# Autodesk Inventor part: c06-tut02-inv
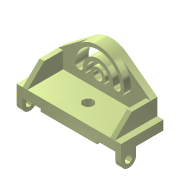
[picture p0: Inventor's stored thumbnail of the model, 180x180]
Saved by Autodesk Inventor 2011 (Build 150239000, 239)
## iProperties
Created: 2010-03
Part Number: c06-tut02-inv
Document SubType Name: Modeling
Designer: CADSoft
Density: 1 g/cm^3
Author: CADSoft
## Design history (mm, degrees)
sketch "Sketch1"
  geometry: 1 further point
sketch "Sketch2"
  geometry: L1 (0, 20)-(-222, 20); L2 (-222, 20)-(-222, 0); L3 (0, 0)-(0, 20); L4 (-171, 0)-(-171, -6); L5 (-171, -6)-(-51, -6); L6 (-51, -6)-(-51, 0); L7 (-222, 0)-(-171, 0); L8 (-51, 0)-(0, 0); 1 further point
  constraints: 16 end point, 4 horizontal, 4 vertical, 2 equal length, 1 coincident
  dimensions: "d0" = 20 distance of L3.start L1.start; "d1" = 26 distance between parallel lines of L5 L1; "d2" = 120 distance of L4.end L5.end; "d3" = 51 distance of L6.end L3.start
extrude "Extrusion1" new body sketch "Sketch2" distance "d4" = 90; taper "d5" = 0 deg
sketch "Sketch3"
  geometry: L1 (209, -20)-(209, -55); L2 (209, -55)-(144.749, -103.524); L3 (77.251, -103.524)-(13, -55); L4 (13, -55)-(13, -20); L5 (13, -20)-(209, -20); L6 (222, -20)-(0, -20) reference; L7 (222, 0)-(222, -20) reference; L8 (0, -20)-(0, 0) reference; A1 r 56 centre (111, -58.836) between (77.251, -103.524) and (144.749, -103.524)
  constraints: 10 end point, 2 equal length, 2 point on circle, 2 tangent, 2 vertical, 1 centre point, 1 horizontal, 1 point on line
  dimensions: "d6" = 35 distance of L1.start L1.end; "d7" = 13 distance between parallel lines of L7 L1; "d8" = 13 distance between parallel lines of L4 L8; "d9" = 56 radius of A1
extrude "Extrusion2" join sketch "Sketch3" distance "d10" = 14; taper "d11" = 0 deg
sketch "Sketch4"
  geometry: C1 r 16 at (111, 58.836); A1 r 56 centre (111, 58.836) between (144.749, 103.524) and (77.251, 103.524) reference; A2 r 24 centre (111, 58.836) between (135, 58.836) and (87, 58.836); A3 r 56 centre (111, 58.836) between (167, 58.836) and (55, 58.836); A4 r 16 centre (71, 58.836) between (55, 58.836) and (87, 58.836); A5 r 16 centre (151, 58.836) between (135, 58.836) and (167, 58.836); 1 further point
  constraints: 8 point on circle, 5 centre point, 4 tangent, 3 coincident, 2 horizontal alignment
  dimensions: "d12" = 56 radius of A3; "d14" = 24 radius of A2; "d15" = 32 diameter of C1
extrude "Extrusion3" join sketch "Sketch4" distance "d16" = 14; taper "d17" = 0 deg
sketch "Sketch5"
  geometry: C1 r 9 at (111, 58.836); A1 r 16 centre (151, 58.836) between (135, 58.836) and (167, 58.836) reference; A2 r 56 centre (111, 58.836) between (167, 58.836) and (55, 58.836) reference; A3 r 16 centre (71, 58.836) between (55, 58.836) and (87, 58.836) reference; A4 r 24 centre (111, 58.836) between (135, 58.836) and (87, 58.836) reference; A5 r 48 centre (111, 58.836) between (159, 58.836) and (63, 58.836); A6 r 8 centre (151, 58.836) between (143, 58.836) and (159, 58.836); A7 r 32 centre (111, 58.836) between (143, 58.836) and (79, 58.836); A8 r 8 centre (71, 58.836) between (63, 58.836) and (79, 58.836); 1 further point
  constraints: 8 point on circle, 5 centre point, 1 coincident, 3 other
  dimensions: "d18" = 8 radius of A8; "d19" = 18 diameter of C1
extrude "Extrusion4" cut sketch "Sketch5" stored distance "d20" = 14; taper "d21" = 0 deg
sketch "Sketch6"
  geometry: L1 (35, -90)-(0, -54); L2 (0, -54)-(0, -14); 2 further points
  constraints: 4 end point, 1 coincident
  dimensions: "d22" = 40 distance of L1.end L2.end
feature "Rib1" sketch "Sketch6" dims "d23" = 1, "d24" = 10, "d25" = 0
sketch "Sketch7"
  geometry: L1 (0, 0)-(0, 90) reference; L2 (0, 0)-(0, 32); L3 (0, 32)-(36, 32); L4 (36, 0)-(0, 0); C1 r 8 at (36, 16); A1 r 16 centre (36, 16) between (36, 0) and (36, 32)
  constraints: 6 end point, 2 centre point, 2 horizontal, 2 point on circle, 2 tangent, 1 coincident, 1 point on line
  dimensions: "d26" = 36 distance of L4.start L1.start; "d27" = 16 radius of A1; "d28" = 16 diameter of C1
extrude "Extrusion5" join sketch "Sketch7" distance "d29" = 12; taper "d30" = 0 deg
workplane "Work Plane1"
mirror "Mirror1"
hole "Hole1" diameter "d34" = 22; stored, may be unused: countersink angle "d38" = 90 deg, drill point angle "d40" = 118 deg; dims "d32" = 88, "d33" = 41, "d35" = 6, "d36" = 4, "d37" = 2, "d39" = 8
body "Solid1"
other parameters: "d31" = -111
